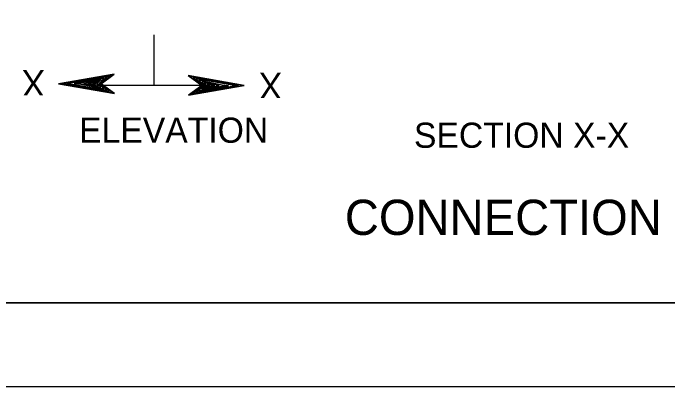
# Model space of a CAD drawing. Extents: x 499883 to 500983, y 499104 to 499764.
# Drawn here: x 500568.6 to 500685.6, y 499103.6 to 499170.5 of the extents above; entities that cross this region are included whole.
import ezdxf

# ---------------------------------------------------------------- set-up
doc = ezdxf.new("R2010")
doc.units = 0
for name, color, linetype in [('1', 7, 'Continuous'), ('2', 7, 'Continuous'), ('41', 7, 'Continuous'), ('5', 7, 'Continuous')]:
    doc.layers.add(name, color=color, linetype=linetype)

msp = doc.modelspace()

# ---------------------------------------------------------------- linework, layer by layer
at = {"layer": '1'}
for p, q in [((499989.94, 499118.64), (500979.94, 499118.64)), ((500982.94, 499103.64), (499934.77, 499103.64))]:
    msp.add_line(p, q, dxfattribs=at)
at = {"layer": '2'}
msp.add_line((500593.78, 499166.55), (500593.78, 499157.53), dxfattribs=at)
at = {"layer": '41'}
for points in [[(499934.77, 499763.64), (500982.94, 499763.64), (500982.94, 499103.64), (499934.77, 499103.64)], [(499989.94, 499748.64), (500979.94, 499748.64), (500979.94, 499118.64), (499989.94, 499118.64)]]:
    msp.add_lwpolyline(points, close=True, dxfattribs=at)
at = {"layer": '5'}
for p, q in [((500593.78, 499157.53), (500583.79, 499157.53)), ((500603.77, 499157.53), (500593.78, 499157.53))]:
    msp.add_line(p, q, dxfattribs=at)
for points in [[(500576.75, 499157.84), (500586.72, 499156.07), (500584.34, 499157.84), (500586.67, 499159.57), (500576.75, 499157.84), (500577.41, 499157.85), (500586.44, 499156.2), (500584.15, 499157.86), (500586.27, 499159.43), (500577.77, 499157.88), (500578.1, 499157.84), (500585.84, 499156.46), (500584.1, 499157.86), (500585.88, 499159.21), (500578.25, 499157.84), (500578.58, 499157.88), (500585.35, 499156.66), (500584.03, 499157.84), (500585.37, 499159.05), (500579.55, 499157.89), (500580.11, 499157.89), (500584.84, 499156.92), (500583.92, 499157.81), (500584.91, 499158.8), (500580.21, 499157.84), (500580.74, 499157.81), (500584.3, 499157.2), (500583.62, 499157.89), (500584.36, 499158.57), (500581.23, 499157.84), (500581.73, 499157.79), (500583.87, 499157.38), (500583.52, 499157.86), (500584.1, 499158.39), (500581.99, 499157.83), (500583.39, 499157.5), (500583.19, 499157.89), (500583.8, 499158.27), (500582.34, 499157.89), (500583.26, 499157.66), (500582.88, 499157.96), (500583.32, 499158.14), (500582.88, 499157.86), (500583.11, 499157.81)], [(500609.91, 499157.53), (500599.93, 499159.3), (500602.32, 499157.53), (500599.99, 499155.8), (500609.91, 499157.53), (500609.24, 499157.52), (500600.21, 499159.17), (500602.5, 499157.51), (500600.39, 499155.94), (500608.89, 499157.49), (500608.55, 499157.53), (500600.82, 499158.91), (500602.55, 499157.51), (500600.77, 499156.16), (500608.4, 499157.53), (500608.07, 499157.49), (500601.31, 499158.71), (500602.62, 499157.53), (500601.28, 499156.32), (500607.11, 499157.48), (500606.54, 499157.48), (500601.81, 499158.45), (500602.73, 499157.56), (500601.74, 499156.57), (500606.44, 499157.53), (500605.91, 499157.56), (500602.35, 499158.17), (500603.04, 499157.48), (500602.29, 499156.8), (500605.42, 499157.53), (500604.92, 499157.58), (500602.78, 499157.99), (500603.13, 499157.51), (500602.55, 499156.98), (500604.66, 499157.54), (500603.27, 499157.87), (500603.47, 499157.48), (500602.86, 499157.1), (500604.31, 499157.48), (500603.39, 499157.71), (500603.78, 499157.41), (500603.34, 499157.23), (500603.78, 499157.51), (500603.55, 499157.56)]]:
    msp.add_lwpolyline(points, dxfattribs=at)

# ---------------------------------------------------------------- texts
for p in [(500574.27, 499160.26), (500616.62, 499159.81)]:
    msp.add_text('X', height=4.5, rotation=180, dxfattribs=at).set_placement(p)
for s, height, p in [('ELEVATION', 4.5, (500580.42, 499147.28)), ('SECTION X-X', 4.5, (500640.24, 499146.38)), ('CONNECTION KEY', 6.2992, (500627.89, 499130.8))]:
    msp.add_text(s, height=height, dxfattribs=at).set_placement(p)

doc.saveas('drawing.dxf')
